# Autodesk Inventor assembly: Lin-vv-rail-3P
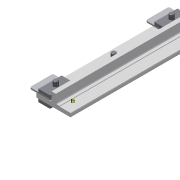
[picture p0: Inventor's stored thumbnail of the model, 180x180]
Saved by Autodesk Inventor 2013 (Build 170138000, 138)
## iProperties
Created: 2012-05
Part Number: Lin-vv-rail-3P
Document SubType Name: Assembly
Designer: ssc
Mass: 102466 g
Surface Area: 32344.9 cm^2
Volume: 13122.6 cm^3
Density: 7.80836 g/cm^3
Description: RAIL ASSEMBLY
Author: ssc
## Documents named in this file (7)
- C:\VaultWorkspace\yh63\Vault\Draft\archive\7100 ERL\Main Component Sub-Asms\7103-000 Main Linac Cryomod\7103-153 Vacuum Vessel\Lin-vv-rail.iam
- C:\VaultWorkspace\yh63\Vault\Draft\archive\7100 ERL\Main Component Sub-Asms\7103-000 Main Linac Cryomod\7103-153 Vacuum Vessel\Lin-vv-rail shim.ipt
- C:\VaultWorkspace\yh63\Vault\Draft\archive\7100 ERL\Main Component Sub-Asms\7103-000 Main Linac Cryomod\7103-153 Vacuum Vessel\Lin-vv-rail shim block.ipt
- C:\VaultWorkspace\yh63\Vault\Draft\archive\7100 ERL\Main Component Sub-Asms\7103-000 Main Linac Cryomod\7103-153 Vacuum Vessel\Lin-vv-rail.ipt
- C:\VaultWorkspace\yh63\Vault\Content Center Files\en-US\ANSI B18.3(08)\ANSI B18.3 - 3_8-16 UNC - 1(24).ipt
- C:\VaultWorkspace\yh63\Vault\Content Center Files\en-US\ANSI B18.3(05)\ANSI B18.3 - 3_8-16 UNC - 1.5(31).ipt
- C:\VaultWorkspace\yh63\Vault\Content Center Files\en-US\ANSI B18.22.1\ANSI B18.22.1 - 3_8 - wide - Type A.ipt
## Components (210 placed, 6 different names)
1. Lin-vv-rail:1 — Mate:2, Insert:2, Insert:5
2. Hexagon Socket Set Screw - Flat Point - Inch 3/8-16 UNC x 1:1 — Insert:5
3. Hexagon Socket Set Screw - Flat Point - Inch 3/8-16 UNC x 1:2
4. Hexagon Socket Set Screw - Flat Point - Inch 3/8-16 UNC x 1:3
5. Hexagon Socket Set Screw - Flat Point - Inch 3/8-16 UNC x 1:4
6. Hexagon Socket Set Screw - Flat Point - Inch 3/8-16 UNC x 1:5
7. Hexagon Socket Set Screw - Flat Point - Inch 3/8-16 UNC x 1:6
8. Hexagon Socket Set Screw - Flat Point - Inch 3/8-16 UNC x 1:7
9. Hexagon Socket Set Screw - Flat Point - Inch 3/8-16 UNC x 1:8
10. Hexagon Socket Set Screw - Flat Point - Inch 3/8-16 UNC x 1:9
11. Hexagon Socket Set Screw - Flat Point - Inch 3/8-16 UNC x 1:10
12. Hexagon Socket Set Screw - Flat Point - Inch 3/8-16 UNC x 1:11
13. Hexagon Socket Set Screw - Flat Point - Inch 3/8-16 UNC x 1:12
14. Hexagon Socket Set Screw - Flat Point - Inch 3/8-16 UNC x 1:13
15. Hexagon Socket Set Screw - Flat Point - Inch 3/8-16 UNC x 1:14
16. Hexagon Socket Set Screw - Flat Point - Inch 3/8-16 UNC x 1:15
17. Hexagon Socket Set Screw - Flat Point - Inch 3/8-16 UNC x 1:16
18. Hexagon Socket Set Screw - Flat Point - Inch 3/8-16 UNC x 1:17
19. Hexagon Socket Set Screw - Flat Point - Inch 3/8-16 UNC x 1:18
20. Hexagon Socket Set Screw - Flat Point - Inch 3/8-16 UNC x 1:19
21. Hexagon Socket Set Screw - Flat Point - Inch 3/8-16 UNC x 1:20
22. Hexagon Socket Set Screw - Flat Point - Inch 3/8-16 UNC x 1:21
23. Hexagon Socket Set Screw - Flat Point - Inch 3/8-16 UNC x 1:22
24. Hexagon Socket Set Screw - Flat Point - Inch 3/8-16 UNC x 1:23
25. Hexagon Socket Set Screw - Flat Point - Inch 3/8-16 UNC x 1:24
26. Hexagon Socket Set Screw - Flat Point - Inch 3/8-16 UNC x 1:25
27. Hexagon Socket Set Screw - Flat Point - Inch 3/8-16 UNC x 1:26
28. Hexagon Socket Set Screw - Flat Point - Inch 3/8-16 UNC x 1:27
29. Hexagon Socket Set Screw - Flat Point - Inch 3/8-16 UNC x 1:28
30. Hexagon Socket Set Screw - Flat Point - Inch 3/8-16 UNC x 1:29
31. Hexagon Socket Set Screw - Flat Point - Inch 3/8-16 UNC x 1:30
32. Hexagon Socket Set Screw - Flat Point - Inch 3/8-16 UNC x 1:31
33. Hexagon Socket Set Screw - Flat Point - Inch 3/8-16 UNC x 1:32
34. Hexagon Socket Set Screw - Flat Point - Inch 3/8-16 UNC x 1:33
35. Hexagon Socket Set Screw - Flat Point - Inch 3/8-16 UNC x 1:34
36. Lin-vv-rail shim block:1 — Flush:1, Flush:2, Mate:1
37. Lin-vv-rail shim:2 — Flush:1, Flush:2, Mate:1, Mate:2
38. Hexagon Socket Head Cap Screw - Inch 3/8 - 16 UNC - 1 1/2:1 — Insert:4
39. Plain Washer (Inch) 3/8 - wide - Type A:1 — Insert:3, Insert:4
40. Lin-vv-rail shim block:36 — Insert:2, Insert:3
41. Lin-vv-rail shim block:37
42. Lin-vv-rail shim:3
43. Hexagon Socket Head Cap Screw - Inch 3/8 - 16 UNC - 1 1/2:2
44. Plain Washer (Inch) 3/8 - wide - Type A:2
45. Lin-vv-rail shim block:38
46. Lin-vv-rail shim block:39
47. Lin-vv-rail shim:4
48. Hexagon Socket Head Cap Screw - Inch 3/8 - 16 UNC - 1 1/2:3
49. Plain Washer (Inch) 3/8 - wide - Type A:3
50. Lin-vv-rail shim block:40
51. Lin-vv-rail shim block:41
52. Lin-vv-rail shim:5
53. Hexagon Socket Head Cap Screw - Inch 3/8 - 16 UNC - 1 1/2:4
54. Plain Washer (Inch) 3/8 - wide - Type A:4
55. Lin-vv-rail shim block:42
56. Lin-vv-rail shim block:43
57. Lin-vv-rail shim:6
58. Hexagon Socket Head Cap Screw - Inch 3/8 - 16 UNC - 1 1/2:5
59. Plain Washer (Inch) 3/8 - wide - Type A:5
60. Lin-vv-rail shim block:44
61. Lin-vv-rail shim block:45
62. Lin-vv-rail shim:7
63. Hexagon Socket Head Cap Screw - Inch 3/8 - 16 UNC - 1 1/2:6
64. Plain Washer (Inch) 3/8 - wide - Type A:6
65. Lin-vv-rail shim block:46
66. Lin-vv-rail shim block:47
67. Lin-vv-rail shim:8
68. Hexagon Socket Head Cap Screw - Inch 3/8 - 16 UNC - 1 1/2:7
69. Plain Washer (Inch) 3/8 - wide - Type A:7
70. Lin-vv-rail shim block:48
71. Lin-vv-rail shim block:49
72. Lin-vv-rail shim:9
73. Hexagon Socket Head Cap Screw - Inch 3/8 - 16 UNC - 1 1/2:8
74. Plain Washer (Inch) 3/8 - wide - Type A:8
75. Lin-vv-rail shim block:50
76. Lin-vv-rail shim block:51
77. Lin-vv-rail shim:10
78. Hexagon Socket Head Cap Screw - Inch 3/8 - 16 UNC - 1 1/2:9
79. Plain Washer (Inch) 3/8 - wide - Type A:9
80. Lin-vv-rail shim block:52
81. Lin-vv-rail shim block:53
82. Lin-vv-rail shim:11
83. Hexagon Socket Head Cap Screw - Inch 3/8 - 16 UNC - 1 1/2:10
84. Plain Washer (Inch) 3/8 - wide - Type A:10
85. Lin-vv-rail shim block:54
86. Lin-vv-rail shim block:55
87. Lin-vv-rail shim:12
88. Hexagon Socket Head Cap Screw - Inch 3/8 - 16 UNC - 1 1/2:11
89. Plain Washer (Inch) 3/8 - wide - Type A:11
90. Lin-vv-rail shim block:56
91. Lin-vv-rail shim block:57
92. Lin-vv-rail shim:13
93. Hexagon Socket Head Cap Screw - Inch 3/8 - 16 UNC - 1 1/2:12
94. Plain Washer (Inch) 3/8 - wide - Type A:12
95. Lin-vv-rail shim block:58
96. Lin-vv-rail shim block:59
97. Lin-vv-rail shim:14
98. Hexagon Socket Head Cap Screw - Inch 3/8 - 16 UNC - 1 1/2:13
99. Plain Washer (Inch) 3/8 - wide - Type A:13
100. Lin-vv-rail shim block:60
101. Lin-vv-rail shim block:61
102. Lin-vv-rail shim:15
103. Hexagon Socket Head Cap Screw - Inch 3/8 - 16 UNC - 1 1/2:14
104. Plain Washer (Inch) 3/8 - wide - Type A:14
105. Lin-vv-rail shim block:62
106. Lin-vv-rail shim block:63
107. Lin-vv-rail shim:16
108. Hexagon Socket Head Cap Screw - Inch 3/8 - 16 UNC - 1 1/2:15
109. Plain Washer (Inch) 3/8 - wide - Type A:15
110. Lin-vv-rail shim block:64
111. Lin-vv-rail shim block:65
112. Lin-vv-rail shim:17
113. Hexagon Socket Head Cap Screw - Inch 3/8 - 16 UNC - 1 1/2:16
114. Plain Washer (Inch) 3/8 - wide - Type A:16
115. Lin-vv-rail shim block:66
116. Lin-vv-rail shim block:67
117. Lin-vv-rail shim:18
118. Hexagon Socket Head Cap Screw - Inch 3/8 - 16 UNC - 1 1/2:17
119. Plain Washer (Inch) 3/8 - wide - Type A:17
120. Lin-vv-rail shim block:68
121. Lin-vv-rail shim block:69
122. Lin-vv-rail shim:19
123. Hexagon Socket Head Cap Screw - Inch 3/8 - 16 UNC - 1 1/2:18
124. Plain Washer (Inch) 3/8 - wide - Type A:18
125. Lin-vv-rail shim block:70
126. Lin-vv-rail shim block:71
127. Lin-vv-rail shim:20
128. Hexagon Socket Head Cap Screw - Inch 3/8 - 16 UNC - 1 1/2:19
129. Plain Washer (Inch) 3/8 - wide - Type A:19
130. Lin-vv-rail shim block:72
131. Lin-vv-rail shim block:73
132. Lin-vv-rail shim:21
133. Hexagon Socket Head Cap Screw - Inch 3/8 - 16 UNC - 1 1/2:20
134. Plain Washer (Inch) 3/8 - wide - Type A:20
135. Lin-vv-rail shim block:74
136. Lin-vv-rail shim block:75
137. Lin-vv-rail shim:22
138. Hexagon Socket Head Cap Screw - Inch 3/8 - 16 UNC - 1 1/2:21
139. Plain Washer (Inch) 3/8 - wide - Type A:21
140. Lin-vv-rail shim block:76
141. Lin-vv-rail shim block:77
142. Lin-vv-rail shim:23
143. Hexagon Socket Head Cap Screw - Inch 3/8 - 16 UNC - 1 1/2:22
144. Plain Washer (Inch) 3/8 - wide - Type A:22
145. Lin-vv-rail shim block:78
146. Lin-vv-rail shim block:79
147. Lin-vv-rail shim:24
148. Hexagon Socket Head Cap Screw - Inch 3/8 - 16 UNC - 1 1/2:23
149. Plain Washer (Inch) 3/8 - wide - Type A:23
150. Lin-vv-rail shim block:80
151. Lin-vv-rail shim block:81
152. Lin-vv-rail shim:25
153. Hexagon Socket Head Cap Screw - Inch 3/8 - 16 UNC - 1 1/2:24
154. Plain Washer (Inch) 3/8 - wide - Type A:24
155. Lin-vv-rail shim block:82
156. Lin-vv-rail shim block:83
157. Lin-vv-rail shim:26
158. Hexagon Socket Head Cap Screw - Inch 3/8 - 16 UNC - 1 1/2:25
159. Plain Washer (Inch) 3/8 - wide - Type A:25
160. Lin-vv-rail shim block:84
161. Lin-vv-rail shim block:85
162. Lin-vv-rail shim:27
163. Hexagon Socket Head Cap Screw - Inch 3/8 - 16 UNC - 1 1/2:26
164. Plain Washer (Inch) 3/8 - wide - Type A:26
165. Lin-vv-rail shim block:86
166. Lin-vv-rail shim block:87
167. Lin-vv-rail shim:28
168. Hexagon Socket Head Cap Screw - Inch 3/8 - 16 UNC - 1 1/2:27
169. Plain Washer (Inch) 3/8 - wide - Type A:27
170. Lin-vv-rail shim block:88
171. Lin-vv-rail shim block:89
172. Lin-vv-rail shim:29
173. Hexagon Socket Head Cap Screw - Inch 3/8 - 16 UNC - 1 1/2:28
174. Plain Washer (Inch) 3/8 - wide - Type A:28
175. Lin-vv-rail shim block:90
176. Lin-vv-rail shim block:91
177. Lin-vv-rail shim:30
178. Hexagon Socket Head Cap Screw - Inch 3/8 - 16 UNC - 1 1/2:29
179. Plain Washer (Inch) 3/8 - wide - Type A:29
180. Lin-vv-rail shim block:92
181. Lin-vv-rail shim block:93
182. Lin-vv-rail shim:31
183. Hexagon Socket Head Cap Screw - Inch 3/8 - 16 UNC - 1 1/2:30
184. Plain Washer (Inch) 3/8 - wide - Type A:30
185. Lin-vv-rail shim block:94
186. Lin-vv-rail shim block:95
187. Lin-vv-rail shim:32
188. Hexagon Socket Head Cap Screw - Inch 3/8 - 16 UNC - 1 1/2:31
189. Plain Washer (Inch) 3/8 - wide - Type A:31
190. Lin-vv-rail shim block:96
191. Lin-vv-rail shim block:97
192. Lin-vv-rail shim:33
193. Hexagon Socket Head Cap Screw - Inch 3/8 - 16 UNC - 1 1/2:32
194. Plain Washer (Inch) 3/8 - wide - Type A:32
195. Lin-vv-rail shim block:98
196. Lin-vv-rail shim block:99
197. Lin-vv-rail shim:34
198. Hexagon Socket Head Cap Screw - Inch 3/8 - 16 UNC - 1 1/2:33
199. Plain Washer (Inch) 3/8 - wide - Type A:33
200. Lin-vv-rail shim block:100
201. Lin-vv-rail shim block:101
202. Lin-vv-rail shim:35
203. Hexagon Socket Head Cap Screw - Inch 3/8 - 16 UNC - 1 1/2:34
204. Plain Washer (Inch) 3/8 - wide - Type A:34
205. Lin-vv-rail shim block:102
206. Lin-vv-rail shim block:103
207. Lin-vv-rail shim:36
208. Hexagon Socket Head Cap Screw - Inch 3/8 - 16 UNC - 1 1/2:35
209. Plain Washer (Inch) 3/8 - wide - Type A:35
210. Lin-vv-rail shim block:104
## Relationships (8: Insert 4, Flush 2, Mate 2)
- Flush:1: Lin-vv-rail shim block:1 ↔ Lin-vv-rail shim:2
- Flush:2: Lin-vv-rail shim block:1 ↔ Lin-vv-rail shim:2
- Mate:1: Lin-vv-rail shim block:1 ↔ Lin-vv-rail shim:2
- Mate:2: Lin-vv-rail:1 ↔ Lin-vv-rail shim:2
- Insert:2: Lin-vv-rail:1 ↔ Lin-vv-rail shim block:36
- Insert:3: Plain Washer (Inch) 3/8 - wide - Type A:1 ↔ Lin-vv-rail shim block:36
- Insert:4: Hexagon Socket Head Cap Screw - Inch 3/8 - 16 UNC - 1 1/2:1 ↔ Plain Washer (Inch) 3/8 - wide - Type A:1
- Insert:5: Lin-vv-rail:1 ↔ Hexagon Socket Set Screw - Flat Point - Inch 3/8-16 UNC x 1:1
